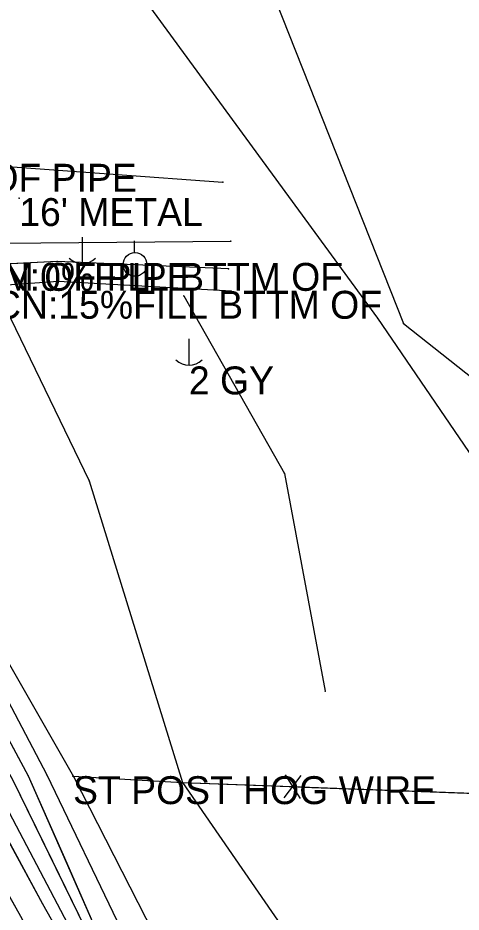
# Model space of a CAD drawing. Extents: x -99999 to 591807, y -99999 to 347168.
# Drawn here: x 589269.6 to 589348.9, y 343805.9 to 343966.1 of the extents above; entities that cross this region are included whole.
import ezdxf

# ---------------------------------------------------------------- set-up
doc = ezdxf.new("R2010")
doc.units = 0
for name, color, linetype in [('S_BREAKLINE', 7, 'Continuous'), ('S_DITCHLINE', 7, 'Continuous'), ('S_DRIVEWAY', 7, 'Continuous'), ('S_EDGE_PAVEMENT', 7, 'Continuous'), ('S_FENCE', 7, 'Continuous'), ('S_FENCE_ANNOT', 7, 'Continuous'), ('S_GATE_ANNOT', 7, 'Continuous'), ('S_GRD_PT_SYM', 7, 'Continuous'), ('S_MSC_PT_SYM', 7, 'Continuous'), ('S_RDW_PT_SYM', 7, 'Continuous'), ('S_SHOULDER', 7, 'Continuous'), ('S_SIDE_DRAIN_ANNOT', 7, 'Continuous'), ('S_UTILITY_POLE', 7, 'Continuous'), ('S_UTILITY_POLE_ANNOT', 7, 'Continuous')]:
    doc.layers.add(name, color=color, linetype=linetype)

msp = doc.modelspace()

# ---------------------------------------------------------------- linework, layer by layer
at = {"layer": 'S_BREAKLINE'}
for points in [[(589259.57, 344046.86), (589287.11, 344015.19), (589313.28, 343975.46), (589338.65, 343911.32), (589374.69, 343882.79), (589378.86, 343824.38), (589432.98, 343780.35), (589441.02, 343746.15)], [(589248.17, 344040.35), (589270.79, 344017.64), (589289.75, 343972.81), (589333.96, 343912.31), (589354.61, 343881.98), (589359.54, 343826.86), (589394.77, 343779.7), (589410.93, 343740.86)], [(589307.83, 343917.09), (589276.8, 343918.85), (589234.94, 343915.87), (589255.44, 343872.29), (589279.54, 343830.17), (589292.52, 343804.79), (589322.97, 343749.69), (589346.46, 343706.11)], [(589265.56, 343917.72), (589282.37, 343883.12), (589299.06, 343829.08), (589343.81, 343764.17), (589361.97, 343718.71)], [(589299.29, 343916.28), (589317.34, 343884.46), (589324.6, 343845.44)], [(589219.72, 343913.97), (589243.69, 343867.82), (589265.54, 343828.39), (589280.92, 343799.18), (589311.54, 343745.76), (589334.69, 343701.69)], [(589253.1, 343871.68), (589274.76, 343830.48), (589288.07, 343802.75), (589319.56, 343748.04), (589343.5, 343706.4)], [(589279.43, 343830.26), (589299.06, 343829.08), (589359.54, 343826.86)]]:
    msp.add_lwpolyline(points, dxfattribs=at)
at = {"layer": 'S_DITCHLINE'}
for points in [[(589307.31, 343921.1), (589276.62, 343922.41), (589233.32, 343920.25), (589225.56, 343915.88)], [(589307.31, 343921.1), (589291.97, 343921.75), (589276.62, 343922.41), (589254.97, 343921.33), (589233.32, 343920.25), (589225.56, 343915.88)], [(589225.56, 343915.88), (589249.83, 343870.46), (589271.45, 343830.32), (589284.4, 343800.85), (589316.11, 343747.23), (589340.1, 343704.21)], [(589225.56, 343915.88), (589231.63, 343904.53), (589237.69, 343893.17), (589243.76, 343881.81), (589249.83, 343870.46), (589260.64, 343850.39), (589271.45, 343830.32), (589277.92, 343815.59), (589284.4, 343800.85), (589292.32, 343787.45), (589300.25, 343774.04), (589308.18, 343760.64), (589316.11, 343747.23), (589328.1, 343725.72), (589340.1, 343704.21)], [(589222.45, 343914.18), (589246.28, 343869.21), (589268.61, 343829.63), (589282.91, 343800.45), (589312.93, 343746.22), (589336.25, 343702.58)], [(589222.45, 343914.18), (589228.41, 343902.94), (589234.36, 343891.69), (589240.32, 343880.45), (589246.28, 343869.21), (589257.45, 343849.42), (589268.61, 343829.63), (589275.76, 343815.04), (589282.91, 343800.45), (589290.42, 343786.89), (589297.92, 343773.34), (589305.43, 343759.78), (589312.93, 343746.22), (589324.59, 343724.4), (589336.25, 343702.58)]]:
    msp.add_lwpolyline(points, dxfattribs=at)
at = {"layer": 'S_DRIVEWAY'}
for points in [[(589223.97, 343937.94), (589267.02, 343939.53), (589306.29, 343936.64)], [(589223.97, 343937.94), (589245.5, 343938.74), (589267.02, 343939.53), (589286.66, 343938.08), (589306.29, 343936.64)], [(589225.7, 343929.65), (589266.88, 343925.7), (589307.69, 343926.06)], [(589225.7, 343929.65), (589246.29, 343927.67), (589266.88, 343925.7), (589287.29, 343925.88), (589307.69, 343926.06)]]:
    msp.add_lwpolyline(points, dxfattribs=at)
at = {"layer": 'S_EDGE_PAVEMENT'}
for points in [[(589044.06, 344210.38), (589062.61, 344176.98), (589089.04, 344129.8), (589108.67, 344094.28), (589125.56, 344064.19), (589145.2, 344028.97), (589161.69, 343999.91), (589175.36, 343974.71), (589194.37, 343940.44), (589208.05, 343916.06), (589231.37, 343874.53), (589249.48, 343841.72), (589270.08, 343805.14), (589289.8, 343769.16), (589308.91, 343733.9), (589328.84, 343697.75)], [(589175.36, 343974.71), (589184.86, 343957.58), (589194.37, 343940.44), (589201.21, 343928.25), (589208.05, 343916.06), (589219.71, 343895.3), (589231.37, 343874.53), (589240.42, 343858.13), (589249.48, 343841.72), (589259.78, 343823.43), (589270.08, 343805.14), (589279.94, 343787.15), (589289.8, 343769.16), (589299.35, 343751.53), (589308.91, 343733.9), (589318.88, 343715.83), (589328.84, 343697.75)]]:
    msp.add_lwpolyline(points, dxfattribs=at)
at = {"layer": 'S_FENCE'}
for p, q in [((589279.47, 343830.23), (589299.06, 343829.08)), ((589317.28, 343826.36), (589320.3, 343830.35)), ((589317.43, 343830.45), (589320.15, 343826.25)), ((589299.06, 343829.08), (589359.54, 343826.86))]:
    msp.add_line(p, q, dxfattribs=at)
for points in [[(589279.47, 343830.23), (589299.06, 343829.08)], [(589299.06, 343829.08), (589317, 343828.42)], [(589320.58, 343828.29), (589356.46, 343826.97)]]:
    msp.add_lwpolyline(points, dxfattribs=at)
at = {"layer": 'S_GRD_PT_SYM'}
for points in [[(589276.62, 343922.41), (589276.62, 343922.36), (589276.62, 343922.41), (589276.67, 343922.41), (589276.62, 343922.41), (589276.62, 343922.46), (589276.62, 343922.41), (589276.57, 343922.41)], [(589307.31, 343921.1), (589307.31, 343921.05), (589307.31, 343921.1), (589307.36, 343921.1), (589307.31, 343921.1), (589307.32, 343921.15), (589307.31, 343921.1), (589307.26, 343921.1)], [(589276.8, 343918.85), (589276.8, 343918.8), (589276.8, 343918.85), (589276.85, 343918.86), (589276.8, 343918.85), (589276.8, 343918.9), (589276.8, 343918.85), (589276.75, 343918.85)], [(589299.29, 343916.28), (589299.33, 343916.31), (589299.29, 343916.28), (589299.26, 343916.33), (589299.29, 343916.28), (589299.24, 343916.26), (589299.29, 343916.28), (589299.31, 343916.24)], [(589307.83, 343917.09), (589307.82, 343917.04), (589307.83, 343917.09), (589307.88, 343917.08), (589307.83, 343917.09), (589307.83, 343917.14), (589307.83, 343917.09), (589307.78, 343917.09)], [(589333.96, 343912.31), (589334, 343912.34), (589333.96, 343912.31), (589333.93, 343912.35), (589333.96, 343912.31), (589333.92, 343912.28), (589333.96, 343912.31), (589333.99, 343912.27)], [(589338.65, 343911.32), (589338.68, 343911.36), (589338.65, 343911.32), (589338.61, 343911.35), (589338.65, 343911.32), (589338.62, 343911.28), (589338.65, 343911.32), (589338.69, 343911.29)], [(589317.34, 343884.46), (589317.39, 343884.47), (589317.34, 343884.46), (589317.33, 343884.51), (589317.34, 343884.46), (589317.29, 343884.45), (589317.34, 343884.46), (589317.35, 343884.41)], [(589282.37, 343883.12), (589282.41, 343883.13), (589282.37, 343883.12), (589282.35, 343883.16), (589282.37, 343883.12), (589282.32, 343883.1), (589282.37, 343883.12), (589282.38, 343883.07)], [(589324.6, 343845.44), (589324.64, 343845.45), (589324.6, 343845.44), (589324.59, 343845.49), (589324.6, 343845.44), (589324.55, 343845.43), (589324.6, 343845.44), (589324.6, 343845.39)], [(589271.45, 343830.32), (589271.49, 343830.34), (589271.45, 343830.32), (589271.43, 343830.36), (589271.45, 343830.32), (589271.4, 343830.3), (589271.45, 343830.32), (589271.47, 343830.27)], [(589274.76, 343830.48), (589274.8, 343830.5), (589274.76, 343830.48), (589274.73, 343830.53), (589274.76, 343830.48), (589274.71, 343830.46), (589274.76, 343830.48), (589274.78, 343830.44)], [(589279.43, 343830.26), (589279.43, 343830.31), (589279.43, 343830.26), (589279.38, 343830.26), (589279.43, 343830.26), (589279.43, 343830.21), (589279.43, 343830.26), (589279.48, 343830.25)], [(589279.54, 343830.17), (589279.58, 343830.19), (589279.54, 343830.17), (589279.52, 343830.21), (589279.54, 343830.17), (589279.5, 343830.15), (589279.54, 343830.17), (589279.56, 343830.13)], [(589299.06, 343829.08), (589299.06, 343829.13), (589299.06, 343829.08), (589299.01, 343829.08), (589299.06, 343829.08), (589299.05, 343829.03), (589299.06, 343829.08), (589299.11, 343829.07)], [(589299.06, 343829.08), (589299.1, 343829.1), (589299.06, 343829.08), (589299.03, 343829.12), (589299.06, 343829.08), (589299.02, 343829.05), (589299.06, 343829.08), (589299.09, 343829.03)]]:
    msp.add_lwpolyline(points, close=True, dxfattribs=at)
at = {"layer": 'S_MSC_PT_SYM'}
for points in [[(589269.84, 343933.79), (589269.84, 343933.84), (589269.84, 343933.79), (589269.79, 343933.79), (589269.84, 343933.79), (589269.84, 343933.74), (589269.84, 343933.79), (589269.89, 343933.79)], [(589279.47, 343830.23), (589279.47, 343830.28), (589279.47, 343830.23), (589279.42, 343830.23), (589279.47, 343830.23), (589279.47, 343830.18), (589279.47, 343830.23), (589279.52, 343830.23)], [(589299.06, 343829.08), (589299.06, 343829.13), (589299.06, 343829.08), (589299.01, 343829.08), (589299.06, 343829.08), (589299.06, 343829.03), (589299.06, 343829.08), (589299.11, 343829.08)]]:
    msp.add_lwpolyline(points, dxfattribs=at)
at = {"layer": 'S_RDW_PT_SYM'}
for points in [[(589306.29, 343936.64), (589306.29, 343936.69), (589306.29, 343936.64), (589306.24, 343936.64), (589306.29, 343936.64), (589306.29, 343936.59), (589306.29, 343936.64), (589306.34, 343936.63)], [(589307.69, 343926.06), (589307.69, 343926.11), (589307.69, 343926.06), (589307.64, 343926.06), (589307.69, 343926.06), (589307.69, 343926.01), (589307.69, 343926.06), (589307.74, 343926.06)], [(589274.01, 343807.37), (589274.05, 343807.39), (589274.01, 343807.37), (589273.99, 343807.41), (589274.01, 343807.37), (589273.97, 343807.34), (589274.01, 343807.37), (589274.04, 343807.32)]]:
    msp.add_lwpolyline(points, close=True, dxfattribs=at)
at = {"layer": 'S_SHOULDER'}
for points in [[(589213.01, 343916.47), (589235.09, 343876.73), (589253.9, 343844.33), (589274.01, 343807.37), (589294.29, 343771.45), (589313.17, 343736.4), (589332.94, 343700.87)], [(589213.01, 343916.47), (589224.05, 343896.6), (589235.09, 343876.73), (589244.49, 343860.53), (589253.9, 343844.33), (589263.95, 343825.85), (589274.01, 343807.37), (589284.15, 343789.41), (589294.29, 343771.45), (589303.73, 343753.93), (589313.17, 343736.4), (589323.05, 343718.63), (589332.94, 343700.87)]]:
    msp.add_lwpolyline(points, dxfattribs=at)
at = {"layer": 'S_UTILITY_POLE'}
for p, q in [((589281.09, 343926.78), (589281.09, 343922.06)), ((589290.44, 343924.05), (589290.44, 343926.16)), ((589300.19, 343908.57), (589300.19, 343903.85))]:
    msp.add_line(p, q, dxfattribs=at)
msp.add_circle((589290.56, 343921.91), 2.13, dxfattribs=at)
for centre in [(589281.15, 343925.48), (589300.25, 343907.27)]:
    msp.add_arc(centre, 3.41, 226.3972, 313.6028, dxfattribs=at)

# ---------------------------------------------------------------- texts
at = {"layer": 'S_FENCE_ANNOT'}
msp.add_text('ST POST HOG WIRE', height=5, dxfattribs=at).set_placement((589279.47, 343825.23))
at = {"layer": 'S_GATE_ANNOT'}
msp.add_text("16' METAL", height=5, dxfattribs=at).set_placement((589269.84, 343928.79))
at = {"layer": 'S_SIDE_DRAIN_ANNOT'}
for s, p in [('CN:0%FILL BTTM OF PIPE', (589208.03, 343934.93)), ('CN:0%FILL BTTM OF PIPE', (589217.84, 343917.18)), ('DI:16 TY:RCP CN:0%FILL BTTM OF ', (589217.84, 343917.18)), ('DI:16 TY:CMP CN:15%FILL BTTM OF', (589220.36, 343912.18))]:
    msp.add_text(s, height=5, dxfattribs=at).set_placement(p)
at = {"layer": 'S_UTILITY_POLE_ANNOT'}
msp.add_text('2 GY', height=5, dxfattribs=at).set_placement((589300.21, 343898.63))

doc.saveas('drawing.dxf')
